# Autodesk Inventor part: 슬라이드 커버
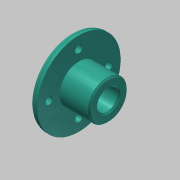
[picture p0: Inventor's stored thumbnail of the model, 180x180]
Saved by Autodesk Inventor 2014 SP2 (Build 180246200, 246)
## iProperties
Created: 2015-12
Part Number: 슬라이드 커버
Document SubType Name: Modeling
Designer: mdu
Density: 2.71 g/cm^3
Material: 알루미늄 6061
Mass: 49.5251 g
Surface Area: 80.5945 cm^2
Volume: 18.2749 cm^3
Appearance: 알루미늄 - 평지
Author: mdu
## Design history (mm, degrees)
sketch "스케치1"
  geometry: L1 (-12.5, 0)-(12.5, 0); L2 (-12.5, 0)-(-12.5, 28); L3 (-12.5, 28)-(-7.5, 28); L4 (-7.5, 28)-(-7.5, 13); L5 (-7.5, 13)-(12.5, 13); L6 (12.5, 13)-(12.5, 0); 2 further points
  constraints: 12 end point, 3 perpendicular, 1 coincident, 1 horizontal, 1 midpoint, 1 parallel
  dimensions: "d1" = 56 diameter of L3 L1; "d2" = 26 diameter of L5 L1; "d5" = 5 distance of L2.end L3.end; "d32" = 20 distance of L4.end L5.end
revolve "회전1" sketch "스케치1" stored, may be unused: angle "d6" = 90 deg
sketch "스케치2" dims "d33" = 40
  geometry: 3 further points
  constraints: 2 vertical alignment, 1 coincident, 2 other
hole "구멍1" sketch "스케치2" at (0, 20) diameter "d8" = 5; stored, may be unused: countersink angle "d12" = 90 deg, drill point angle "d14" = 118 deg; dims "d9" = 6, "d10" = 8, "d11" = 4.4, "d13" = 8
hole "구멍2" diameter "d20" = 14; stored, may be unused: countersink angle "d24" = 90 deg, drill point angle "d26" = 0 deg; dims "d18" = 10, "d19" = 10, "d21" = 6, "d22" = 8, "d23" = 4.4, "d25" = 8
fillet "모깎기1" dims "d27" = 3
chamfer "모따기1" distance "d29" = 1; stored, may be unused: second distance "d30" = 2, angle "d31" = 45 deg
node "솔리드1"
pattern_circular "원형 패턴1" dims angle "d16" = 360 deg
